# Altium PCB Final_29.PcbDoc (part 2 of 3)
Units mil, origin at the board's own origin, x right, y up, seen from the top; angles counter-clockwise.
Board outline 11000 x 6000 mil, 4 copper layers (TopLayer, MidLayer1, MidLayer2, BottomLayer), stack 29.222 mil thick; 209 components, 95 nets, 681 pads, 861 vias.
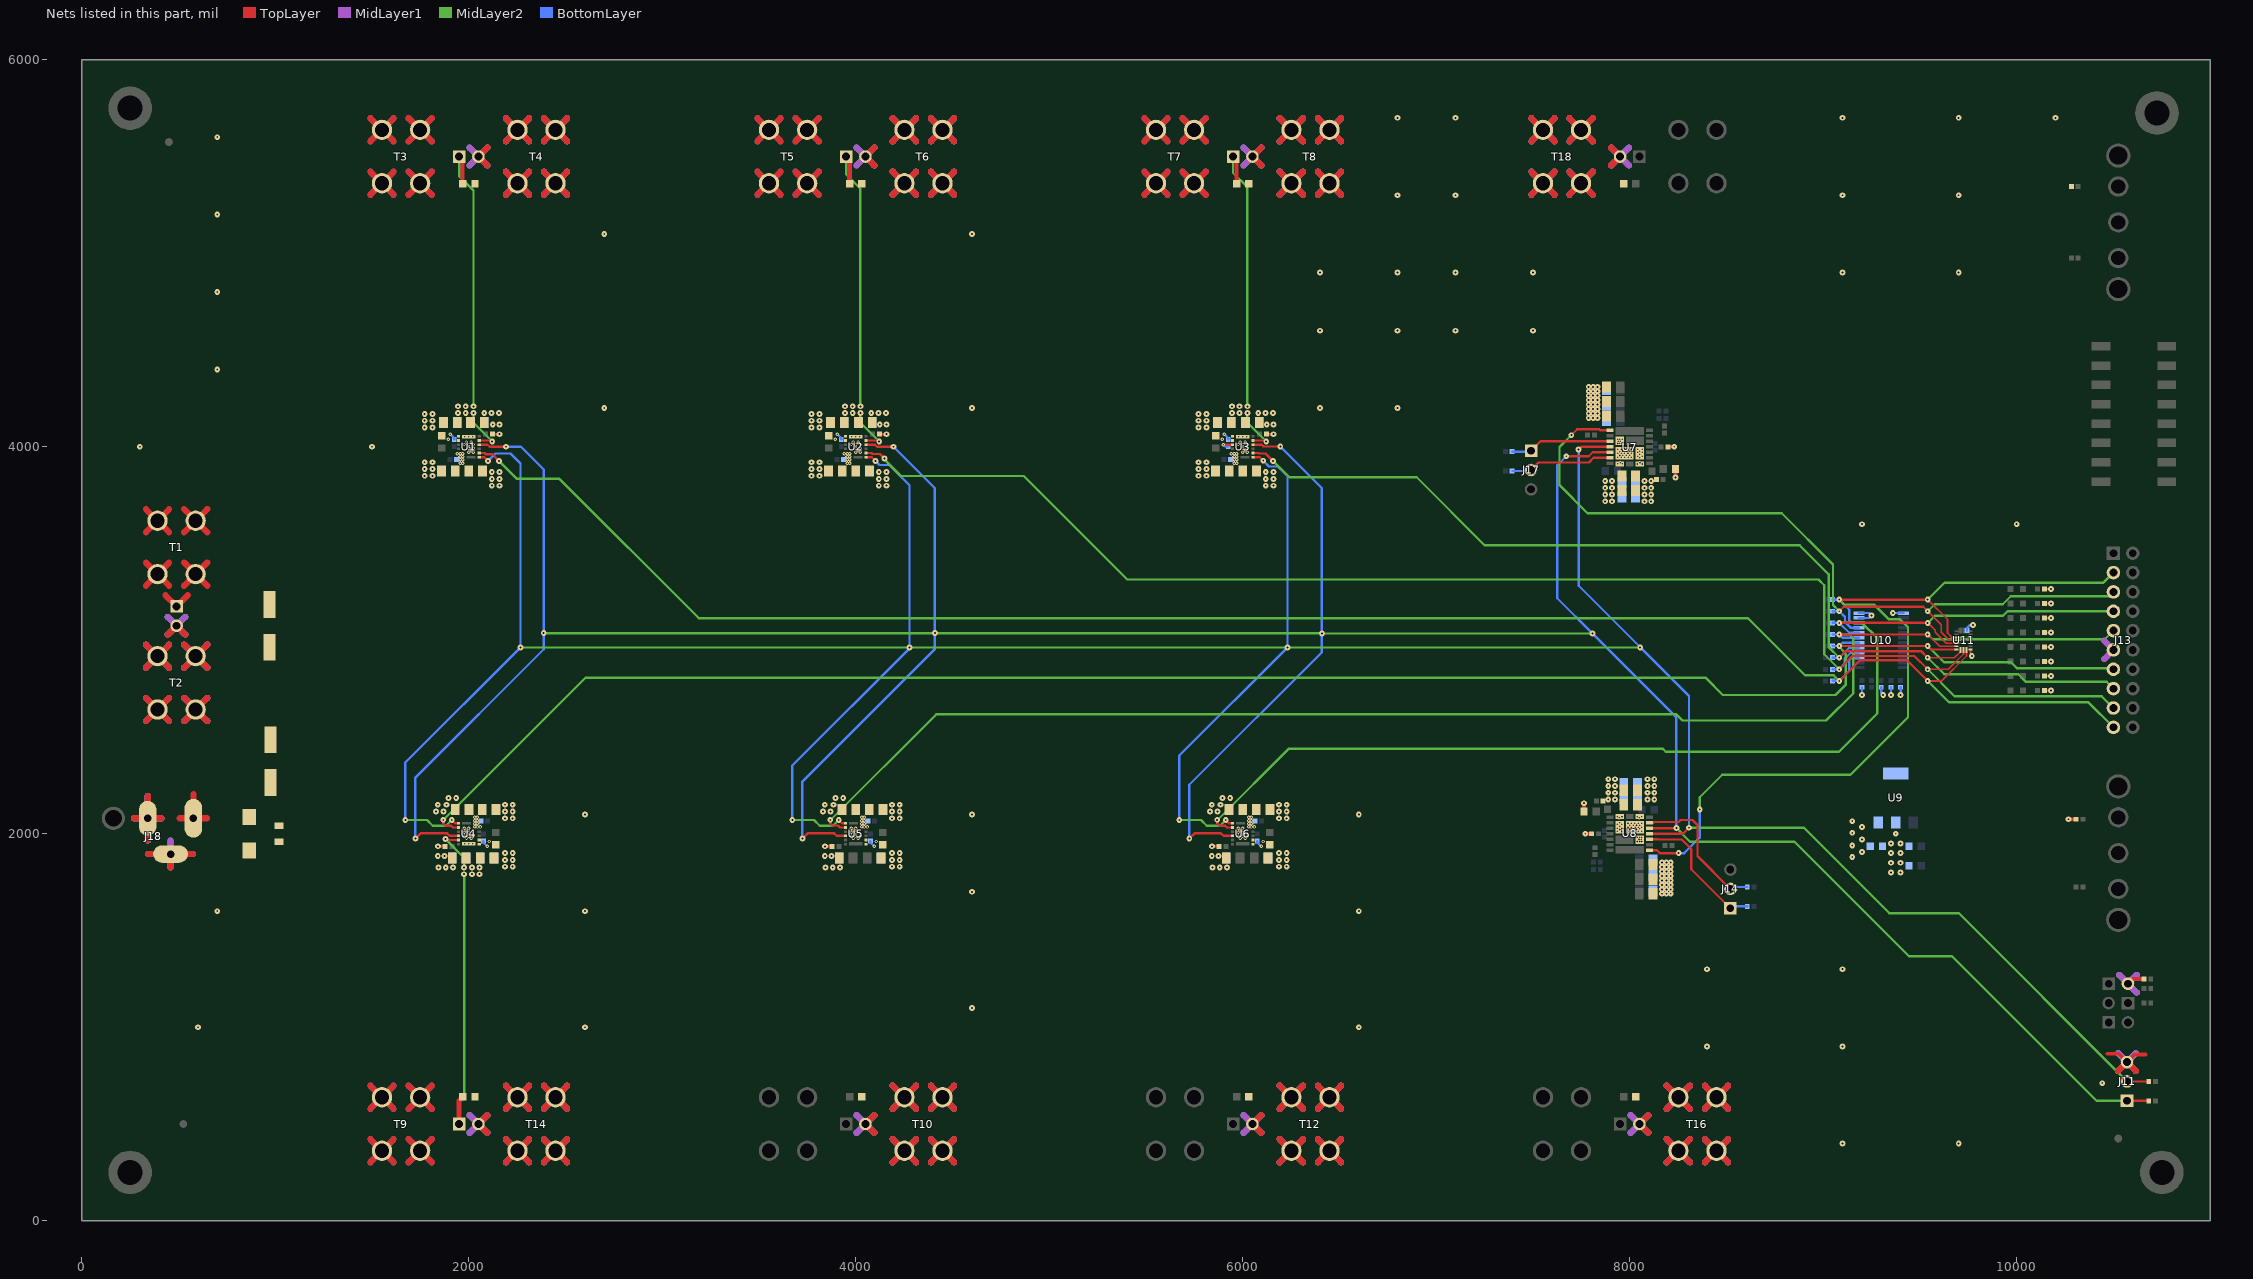
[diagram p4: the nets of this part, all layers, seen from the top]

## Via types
v1: diameter 30, hole 10, TopLayer to BottomLayer, tented both sides, 493 vias
v2: diameter 18, hole 8, TopLayer to BottomLayer, tented both sides, 308 vias
v3: diameter 18, hole 8, TopLayer to BottomLayer, tented bottom, 60 vias

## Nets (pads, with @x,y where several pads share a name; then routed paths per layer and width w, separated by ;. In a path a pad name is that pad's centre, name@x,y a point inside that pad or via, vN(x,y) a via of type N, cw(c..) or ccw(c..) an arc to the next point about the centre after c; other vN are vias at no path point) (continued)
PGND: C1.1 C2.1 C3.1 C4.2 C5.2 C7.1 C8.1 C9.1 C10.2 C11.2 C13.1 C14.1 C15.1 C16.2 C17.2 C19.1 C20.1 C21.1 C22.2 C23.2 C25.1 C26.1 C27.1 C28.1 C29.1 C30.1 C31.2 C32.2 C33.2 C34.2 C38.1 C39.1 C40.1 C41.1 C43.1 C45.1 C47.2 C48.2 C49.2 C50.2 C52.2 C53.2 C101.2 C102.1 C103.1 C104.1 C105.1 C106.1 C107.1 C108.1 C109.1 C110.1 C111.1 C112.1 C113.1 C115.1 C116.1 C118.2 C119.2 C120.2 C122.2 C123.2 C124.2 C125.1 C126.1 C128.1 C129.1 C130.1 C131.1 C132.1 C133.1 C134.1 C135.1 C136.1 C137.1 C138.2 C139.2 C140.2 C141.2 C142.2 C143.2 C144.2 C145.2 C146.2 C147.2 C148.2 C149.2 C150.2 C151.2 D15.1 J1.2 J2.2 J3.2 J4.2 J5.2 J6.2 J7.2 J8.2 J9.2 J11.3 J13.11 J18.2 J18.3 J21.2 NT1.2 NT2.1 R3.1 R6.1 R9.1 R12.1 R18.2 R23.1 R24.1 R65.1 R66.1 R67.1 R68.1 R69.1 R70.1 R71.1 R72.1 R73.1 R75.2 R76.2 T2.1 T2.2 T2.3 T2.4 T4.1 T4.2 T4.3 T4.4 T6.1 T6.2 T6.3 T6.4 T8.1 T8.2 T8.3 T8.4 T10.1 T10.2 T10.3 T10.4 T12.1 T12.2 T12.3 T12.4 T14.1 T14.2 T14.3 T14.4 T16.1 T16.2 T16.3 T16.4 T18.1 T18.2 T18.3 T18.4 U1.8 U1.9 U1.16 U2.8 U2.9 U2.16 U3.8 U3.9 U3.16 U4.8 U4.9 U4.16 U5.8 U5.9 U5.16 U6.8 U6.9 U6.16 U7.16 U7.20 U7.21 U8.16 U8.20 U8.21 U9.2 U9.4 U10.11 U10.12 U10.13 U11.11 V1.1 | length 62999.2
  TopLayer w9: U11.11@9760.7,2952.8 9760.7,2926.3 v1(9768,2919)
  TopLayer w12: v1(1841,1935) R12.1@1877.3,1935 ; R3.1@2122.7,4065 v1(2159,4065) ; v1(3841,1935) R23.1@3877.3,1935 ; R6.1@4122.7,4065 v1(4159,4065) ; v1(5841,1935) R24.1@5877.3,1935 ; R9.1@6122.7,4065 v1(6159,4065) ; R66.1@10142.7,2740 v1(10177.7,2740) ; R67.1@10142.7,2815 v1(10177.7,2815) ; R68.1@10142.7,2890 v1(10177.7,2890) ; R69.1@10142.7,2965 v1(10177.7,2965) ; R70.1@10142.7,3040 v1(10177.7,3040) ; R71.1@10142.7,3115 v1(10177.7,3115) ; R72.1@10142.7,3190 v1(10177.7,3190) ; R73.1@10142.7,3265 v1(10177.7,3265)
  TopLayer w20: C115.1@7763.5,2115 v1(7763.5,2158) ; v1(7770,2000) C116.1@7802.3,2000 ; C45.1@8197.7,4000 v1(8230,4000) ; v1(8236.5,3841) C43.1@8236.5,3885 ; v1(10267.3,2075) R75.2@10307.3,2075 ; 10468,863 10527,863 J11.3@10570,820 10610,860 10666,860 ; J21.2@10575,1225 10600,1250 R76.2@10657.3,1250
  TopLayer w32: 270.4,2080 J18.2@340.5,2080 ; 331.6,2582.1 T2.2@391.5,2642 ; 331.6,2701.9 T2.2@391.5,2642 ; 331.6,2858.1 T2.1@391.5,2918 ; 331.6,2977.9 T2.1@391.5,2918 ; 340.5,1964.9 J18.2@340.5,2080 ; 340.5,2195.1 J18.2@340.5,2080 ; 343.5,1895 J18.3@458.6,1895 ; 410.6,2080 J18.2@340.5,2080 ; 444.3,3029.3 J1.2@490,3075 535.7,3029.3 ; 451.4,2582.1 T2.2@391.5,2642 ; 451.4,2701.9 T2.2@391.5,2642 ; 451.4,2858.1 T2.1@391.5,2918 ; 451.4,2977.9 T2.1@391.5,2918 ; 458.6,1824.9 J18.3@458.6,1895 ; 528.6,2582.1 T2.3@588.5,2642 ; 528.6,2701.9 T2.3@588.5,2642 ; 528.6,2858.1 T2.4@588.5,2918 ; 528.6,2977.9 T2.4@588.5,2918 ; 573.7,1895 J18.3@458.6,1895 ; 648.4,2582.1 T2.3@588.5,2642 ; 648.4,2701.9 T2.3@588.5,2642 ; 648.4,2858.1 T2.4@588.5,2918 ; 648.4,2977.9 T2.4@588.5,2918 ; 2095.7,454.3 J5.2@2050,500 2095.7,545.7 ; 2095.7,5454.3 J2.2@2050,5500 2095.7,5545.7 ; 2191.6,302.1 T14.2@2251.5,362 ; 2191.6,421.9 T14.2@2251.5,362 ; 2191.6,578.1 T14.1@2251.5,638 ; 2191.6,697.9 T14.1@2251.5,638 ; 2191.6,5302.1 T4.2@2251.5,5362 ; 2191.6,5421.9 T4.2@2251.5,5362 ; 2191.6,5578.1 T4.1@2251.5,5638 ; 2191.6,5697.9 T4.1@2251.5,5638 ; 2311.4,302.1 T14.2@2251.5,362 ; 2311.4,421.9 T14.2@2251.5,362 ; 2311.4,578.1 T14.1@2251.5,638 ; 2311.4,697.9 T14.1@2251.5,638 ; 2311.4,5302.1 T4.2@2251.5,5362 ; 2311.4,5421.9 T4.2@2251.5,5362 ; 2311.4,5578.1 T4.1@2251.5,5638 ; 2311.4,5697.9 T4.1@2251.5,5638 ; 2388.6,302.1 T14.3@2448.5,362 ; 2388.6,421.9 T14.3@2448.5,362 ; 2388.6,578.1 T14.4@2448.5,638 ; 2388.6,697.9 T14.4@2448.5,638 ; 2388.6,5302.1 T4.3@2448.5,5362 ; 2388.6,5421.9 T4.3@2448.5,5362 ; 2388.6,5578.1 T4.4@2448.5,5638 ; 2388.6,5697.9 T4.4@2448.5,5638 ; 2508.4,302.1 T14.3@2448.5,362 ; 2508.4,421.9 T14.3@2448.5,362 ; 2508.4,578.1 T14.4@2448.5,638 ; 2508.4,697.9 T14.4@2448.5,638 ; 2508.4,5302.1 T4.3@2448.5,5362 ; 2508.4,5421.9 T4.3@2448.5,5362 ; 2508.4,5578.1 T4.4@2448.5,5638 ; 2508.4,5697.9 T4.4@2448.5,5638 ; 4095.7,454.3 J6.2@4050,500 4095.7,545.7 ; 4095.7,5454.3 J3.2@4050,5500 4095.7,5545.7 ; 4191.6,302.1 T10.2@4251.5,362 ; 4191.6,421.9 T10.2@4251.5,362 ; 4191.6,578.1 T10.1@4251.5,638 ; 4191.6,697.9 T10.1@4251.5,638 ; 4191.6,5302.1 T6.2@4251.5,5362 ; 4191.6,5421.9 T6.2@4251.5,5362 ; 4191.6,5578.1 T6.1@4251.5,5638 ; 4191.6,5697.9 T6.1@4251.5,5638 ; 4311.4,302.1 T10.2@4251.5,362 ; 4311.4,421.9 T10.2@4251.5,362 ; 4311.4,578.1 T10.1@4251.5,638 ; 4311.4,697.9 T10.1@4251.5,638 ; 4311.4,5302.1 T6.2@4251.5,5362 ; 4311.4,5421.9 T6.2@4251.5,5362 ; 4311.4,5578.1 T6.1@4251.5,5638 ; 4311.4,5697.9 T6.1@4251.5,5638 ; 4388.6,302.1 T10.3@4448.5,362 ; 4388.6,421.9 T10.3@4448.5,362 ; 4388.6,578.1 T10.4@4448.5,638 ; 4388.6,697.9 T10.4@4448.5,638 ; 4388.6,5302.1 T6.3@4448.5,5362 ; 4388.6,5421.9 T6.3@4448.5,5362 ; 4388.6,5578.1 T6.4@4448.5,5638 ; 4388.6,5697.9 T6.4@4448.5,5638 ; 4508.4,302.1 T10.3@4448.5,362 ; 4508.4,421.9 T10.3@4448.5,362 ; 4508.4,578.1 T10.4@4448.5,638 ; 4508.4,697.9 T10.4@4448.5,638 ; 4508.4,5302.1 T6.3@4448.5,5362 ; 4508.4,5421.9 T6.3@4448.5,5362 ; 4508.4,5578.1 T6.4@4448.5,5638 ; 4508.4,5697.9 T6.4@4448.5,5638 ; 6095.7,454.3 J7.2@6050,500 6095.7,545.7 ; 6095.7,5454.3 J4.2@6050,5500 6095.7,5545.7 ; 6191.6,302.1 T12.2@6251.5,362 ; 6191.6,421.9 T12.2@6251.5,362 ; 6191.6,578.1 T12.1@6251.5,638 ; 6191.6,697.9 T12.1@6251.5,638 ; 6191.6,5302.1 T8.2@6251.5,5362 ; 6191.6,5421.9 T8.2@6251.5,5362 ; 6191.6,5578.1 T8.1@6251.5,5638 ; 6191.6,5697.9 T8.1@6251.5,5638 ; 6311.4,302.1 T12.2@6251.5,362 ; 6311.4,421.9 T12.2@6251.5,362 ; 6311.4,578.1 T12.1@6251.5,638 ; 6311.4,697.9 T12.1@6251.5,638 ; 6311.4,5302.1 T8.2@6251.5,5362 ; 6311.4,5421.9 T8.2@6251.5,5362 ; 6311.4,5578.1 T8.1@6251.5,5638 ; 6311.4,5697.9 T8.1@6251.5,5638 ; 6388.6,302.1 T12.3@6448.5,362 ; 6388.6,421.9 T12.3@6448.5,362 ; 6388.6,578.1 T12.4@6448.5,638 ; 6388.6,697.9 T12.4@6448.5,638 ; 6388.6,5302.1 T8.3@6448.5,5362 ; 6388.6,5421.9 T8.3@6448.5,5362 ; 6388.6,5578.1 T8.4@6448.5,5638 ; 6388.6,5697.9 T8.4@6448.5,5638 ; 6508.4,302.1 T12.3@6448.5,362 ; 6508.4,421.9 T12.3@6448.5,362 ; 6508.4,578.1 T12.4@6448.5,638 ; 6508.4,697.9 T12.4@6448.5,638 ; 6508.4,5302.1 T8.3@6448.5,5362 ; 6508.4,5421.9 T8.3@6448.5,5362 ; 6508.4,5578.1 T8.4@6448.5,5638 ; 6508.4,5697.9 T8.4@6448.5,5638 ; 7491.6,5302.1 T18.2@7551.5,5362 ; 7491.6,5421.9 T18.2@7551.5,5362 ; 7491.6,5578.1 T18.1@7551.5,5638 ; 7491.6,5697.9 T18.1@7551.5,5638 ; 7611.4,5302.1 T18.2@7551.5,5362 ; 7611.4,5421.9 T18.2@7551.5,5362 ; 7611.4,5578.1 T18.1@7551.5,5638 ; 7611.4,5697.9 T18.1@7551.5,5638 ; 7688.6,5302.1 T18.3@7748.5,5362 ; 7688.6,5421.9 T18.3@7748.5,5362 ; 7688.6,5578.1 T18.4@7748.5,5638 ; 7688.6,5697.9 T18.4@7748.5,5638 ; 7808.4,5302.1 T18.3@7748.5,5362 ; 7808.4,5421.9 T18.3@7748.5,5362 ; 7808.4,5578.1 T18.4@7748.5,5638 ; 7808.4,5697.9 T18.4@7748.5,5638 ; 7904.3,5454.3 J9.2@7950,5500 7904.3,5545.7 ; 8095.7,454.3 J8.2@8050,500 8095.7,545.7 ; 8191.6,302.1 T16.2@8251.5,362 ; 8191.6,421.9 T16.2@8251.5,362 ; 8191.6,578.1 T16.1@8251.5,638 ; 8191.6,697.9 T16.1@8251.5,638 ; 8311.4,302.1 T16.2@8251.5,362 ; 8311.4,421.9 T16.2@8251.5,362 ; 8311.4,578.1 T16.1@8251.5,638 ; 8311.4,697.9 T16.1@8251.5,638 ; 8388.6,302.1 T16.3@8448.5,362 ; 8388.6,421.9 T16.3@8448.5,362 ; 8388.6,578.1 T16.4@8448.5,638 ; 8388.6,697.9 T16.4@8448.5,638 ; 8508.4,302.1 T16.3@8448.5,362 ; 8508.4,421.9 T16.3@8448.5,362 ; 8508.4,578.1 T16.4@8448.5,638 ; 8508.4,697.9 T16.4@8448.5,638 ; 10524.3,774.3 J11.3@10570,820 10615.7,774.3
  MidLayer1 w32: 270.4,2080 J18.2@340.5,2080 ; 331.6,2582.1 T2.2@391.5,2642 ; 331.6,2701.9 T2.2@391.5,2642 ; 331.6,2858.1 T2.1@391.5,2918 ; 331.6,2977.9 T2.1@391.5,2918 ; 340.5,1964.9 J18.2@340.5,2080 ; 340.5,2195.1 J18.2@340.5,2080 ; 343.5,1895 J18.3@458.6,1895 ; 410.6,2080 J18.2@340.5,2080 ; 444.3,3029.3 J1.2@490,3075 ; 444.3,3120.7 J1.2@490,3075 ; 451.4,2582.1 T2.2@391.5,2642 ; 451.4,2701.9 T2.2@391.5,2642 ; 451.4,2858.1 T2.1@391.5,2918 ; 451.4,2977.9 T2.1@391.5,2918 ; 458.6,1824.9 J18.3@458.6,1895 ; 458.6,1965.1 J18.3@458.6,1895 ; 528.6,2582.1 T2.3@588.5,2642 ; 528.6,2701.9 T2.3@588.5,2642 ; 528.6,2858.1 T2.4@588.5,2918 ; 528.6,2977.9 T2.4@588.5,2918 ; 535.7,3029.3 J1.2@490,3075 ; 535.7,3120.7 J1.2@490,3075 ; 573.7,1895 J18.3@458.6,1895 ; 648.4,2582.1 T2.3@588.5,2642 ; 648.4,2701.9 T2.3@588.5,2642 ; 648.4,2858.1 T2.4@588.5,2918 ; 648.4,2977.9 T2.4@588.5,2918 ; 2004.3,454.3 J5.2@2050,500 ; 2004.3,545.7 J5.2@2050,500 ; 2004.3,5454.3 J2.2@2050,5500 ; 2004.3,5545.7 J2.2@2050,5500 ; 2095.7,454.3 J5.2@2050,500 ; 2095.7,545.7 J5.2@2050,500 ; 2095.7,5454.3 J2.2@2050,5500 ; 2095.7,5545.7 J2.2@2050,5500 ; 2191.6,302.1 T14.2@2251.5,362 ; 2191.6,421.9 T14.2@2251.5,362 ; 2191.6,578.1 T14.1@2251.5,638 ; 2191.6,697.9 T14.1@2251.5,638 ; 2191.6,5302.1 T4.2@2251.5,5362 ; 2191.6,5421.9 T4.2@2251.5,5362 ; 2191.6,5578.1 T4.1@2251.5,5638 ; 2191.6,5697.9 T4.1@2251.5,5638 ; 2311.4,302.1 T14.2@2251.5,362 ; 2311.4,421.9 T14.2@2251.5,362 ; 2311.4,578.1 T14.1@2251.5,638 ; 2311.4,697.9 T14.1@2251.5,638 ; 2311.4,5302.1 T4.2@2251.5,5362 ; 2311.4,5421.9 T4.2@2251.5,5362 ; 2311.4,5578.1 T4.1@2251.5,5638 ; 2311.4,5697.9 T4.1@2251.5,5638 ; 2388.6,302.1 T14.3@2448.5,362 ; 2388.6,421.9 T14.3@2448.5,362 ; 2388.6,578.1 T14.4@2448.5,638 ; 2388.6,697.9 T14.4@2448.5,638 ; 2388.6,5302.1 T4.3@2448.5,5362 ; 2388.6,5421.9 T4.3@2448.5,5362 ; 2388.6,5578.1 T4.4@2448.5,5638 ; 2388.6,5697.9 T4.4@2448.5,5638 ; 2508.4,302.1 T14.3@2448.5,362 ; 2508.4,421.9 T14.3@2448.5,362 ; 2508.4,578.1 T14.4@2448.5,638 ; 2508.4,697.9 T14.4@2448.5,638 ; 2508.4,5302.1 T4.3@2448.5,5362 ; 2508.4,5421.9 T4.3@2448.5,5362 ; 2508.4,5578.1 T4.4@2448.5,5638 ; 2508.4,5697.9 T4.4@2448.5,5638 ; 4004.3,454.3 J6.2@4050,500 ; 4004.3,545.7 J6.2@4050,500 ; 4004.3,5454.3 J3.2@4050,5500 ; 4004.3,5545.7 J3.2@4050,5500 ; 4095.7,454.3 J6.2@4050,500 ; 4095.7,545.7 J6.2@4050,500 ; 4095.7,5454.3 J3.2@4050,5500 ; 4095.7,5545.7 J3.2@4050,5500 ; 4191.6,302.1 T10.2@4251.5,362 ; 4191.6,421.9 T10.2@4251.5,362 ; 4191.6,578.1 T10.1@4251.5,638 ; 4191.6,697.9 T10.1@4251.5,638 ; 4191.6,5302.1 T6.2@4251.5,5362 ; 4191.6,5421.9 T6.2@4251.5,5362 ; 4191.6,5578.1 T6.1@4251.5,5638 ; 4191.6,5697.9 T6.1@4251.5,5638 ; 4311.4,302.1 T10.2@4251.5,362 ; 4311.4,421.9 T10.2@4251.5,362 ; 4311.4,578.1 T10.1@4251.5,638 ; 4311.4,697.9 T10.1@4251.5,638 ; 4311.4,5302.1 T6.2@4251.5,5362 ; 4311.4,5421.9 T6.2@4251.5,5362 ; 4311.4,5578.1 T6.1@4251.5,5638 ; 4311.4,5697.9 T6.1@4251.5,5638 ; 4388.6,302.1 T10.3@4448.5,362 ; 4388.6,421.9 T10.3@4448.5,362 ; 4388.6,578.1 T10.4@4448.5,638 ; 4388.6,697.9 T10.4@4448.5,638 ; 4388.6,5302.1 T6.3@4448.5,5362 ; 4388.6,5421.9 T6.3@4448.5,5362 ; 4388.6,5578.1 T6.4@4448.5,5638 ; 4388.6,5697.9 T6.4@4448.5,5638 ; 4508.4,302.1 T10.3@4448.5,362 ; 4508.4,421.9 T10.3@4448.5,362 ; 4508.4,578.1 T10.4@4448.5,638 ; 4508.4,697.9 T10.4@4448.5,638 ; 4508.4,5302.1 T6.3@4448.5,5362 ; 4508.4,5421.9 T6.3@4448.5,5362 ; 4508.4,5578.1 T6.4@4448.5,5638 ; 4508.4,5697.9 T6.4@4448.5,5638 ; 6004.3,454.3 J7.2@6050,500 ; 6004.3,545.7 J7.2@6050,500 ; 6004.3,5454.3 J4.2@6050,5500 ; 6004.3,5545.7 J4.2@6050,5500 ; 6095.7,454.3 J7.2@6050,500 ; 6095.7,545.7 J7.2@6050,500 ; 6095.7,5454.3 J4.2@6050,5500 ; 6095.7,5545.7 J4.2@6050,5500 ; 6191.6,302.1 T12.2@6251.5,362 ; 6191.6,421.9 T12.2@6251.5,362 ; 6191.6,578.1 T12.1@6251.5,638 ; 6191.6,697.9 T12.1@6251.5,638 ; 6191.6,5302.1 T8.2@6251.5,5362 ; 6191.6,5421.9 T8.2@6251.5,5362 ; 6191.6,5578.1 T8.1@6251.5,5638 ; 6191.6,5697.9 T8.1@6251.5,5638 ; 6311.4,302.1 T12.2@6251.5,362 ; 6311.4,421.9 T12.2@6251.5,362 ; 6311.4,578.1 T12.1@6251.5,638 ; 6311.4,697.9 T12.1@6251.5,638 ; 6311.4,5302.1 T8.2@6251.5,5362 ; 6311.4,5421.9 T8.2@6251.5,5362 ; 6311.4,5578.1 T8.1@6251.5,5638 ; 6311.4,5697.9 T8.1@6251.5,5638 ; 6388.6,302.1 T12.3@6448.5,362 ; 6388.6,421.9 T12.3@6448.5,362 ; 6388.6,578.1 T12.4@6448.5,638 ; 6388.6,697.9 T12.4@6448.5,638 ; 6388.6,5302.1 T8.3@6448.5,5362 ; 6388.6,5421.9 T8.3@6448.5,5362 ; 6388.6,5578.1 T8.4@6448.5,5638 ; 6388.6,5697.9 T8.4@6448.5,5638 ; 6508.4,302.1 T12.3@6448.5,362 ; 6508.4,421.9 T12.3@6448.5,362 ; 6508.4,578.1 T12.4@6448.5,638 ; 6508.4,697.9 T12.4@6448.5,638 ; 6508.4,5302.1 T8.3@6448.5,5362 ; 6508.4,5421.9 T8.3@6448.5,5362 ; 6508.4,5578.1 T8.4@6448.5,5638 ; 6508.4,5697.9 T8.4@6448.5,5638 ; 7491.6,5302.1 T18.2@7551.5,5362 ; 7491.6,5421.9 T18.2@7551.5,5362 ; 7491.6,5578.1 T18.1@7551.5,5638 ; 7491.6,5697.9 T18.1@7551.5,5638 ; 7611.4,5302.1 T18.2@7551.5,5362 ; 7611.4,5421.9 T18.2@7551.5,5362 ; 7611.4,5578.1 T18.1@7551.5,5638 ; 7611.4,5697.9 T18.1@7551.5,5638 ; 7688.6,5302.1 T18.3@7748.5,5362 ; 7688.6,5421.9 T18.3@7748.5,5362 ; 7688.6,5578.1 T18.4@7748.5,5638 ; 7688.6,5697.9 T18.4@7748.5,5638 ; 7808.4,5302.1 T18.3@7748.5,5362 ; 7808.4,5421.9 T18.3@7748.5,5362 ; 7808.4,5578.1 T18.4@7748.5,5638 ; 7808.4,5697.9 T18.4@7748.5,5638 ; 7904.3,5454.3 J9.2@7950,5500 ; 7904.3,5545.7 J9.2@7950,5500 ; 7995.7,5454.3 J9.2@7950,5500 ; 7995.7,5545.7 J9.2@7950,5500 ; 8004.3,454.3 J8.2@8050,500 ; 8004.3,545.7 J8.2@8050,500 ; 8095.7,454.3 J8.2@8050,500 ; 8095.7,545.7 J8.2@8050,500 ; 8191.6,302.1 T16.2@8251.5,362 ; 8191.6,421.9 T16.2@8251.5,362 ; 8191.6,578.1 T16.1@8251.5,638 ; 8191.6,697.9 T16.1@8251.5,638 ; 8311.4,302.1 T16.2@8251.5,362 ; 8311.4,421.9 T16.2@8251.5,362 ; 8311.4,578.1 T16.1@8251.5,638 ; 8311.4,697.9 T16.1@8251.5,638 ; 8388.6,302.1 T16.3@8448.5,362 ; 8388.6,421.9 T16.3@8448.5,362 ; 8388.6,578.1 T16.4@8448.5,638 ; 8388.6,697.9 T16.4@8448.5,638 ; 8508.4,302.1 T16.3@8448.5,362 ; 8508.4,421.9 T16.3@8448.5,362 ; 8508.4,578.1 T16.4@8448.5,638 ; 8508.4,697.9 T16.4@8448.5,638 ; 10452.5,2902.5 J13.11@10500,2950 10452.5,2997.5 ; 10524.3,774.3 J11.3@10570,820 ; 10524.3,865.7 J11.3@10570,820 ; 10529.3,1270.7 J21.2@10575,1225 ; 10615.7,774.3 J11.3@10570,820 ; 10615.7,865.7 J11.3@10570,820 ; 10620.7,1179.3 J21.2@10575,1225 ; 10620.7,1270.7 J21.2@10575,1225
  MidLayer2 w32: 270.4,2080 J18.2@340.5,2080 ; 331.6,2582.1 T2.2@391.5,2642 ; 331.6,2701.9 T2.2@391.5,2642 ; 331.6,2858.1 T2.1@391.5,2918 ; 331.6,2977.9 T2.1@391.5,2918 ; 340.5,1964.9 J18.2@340.5,2080 ; 340.5,2195.1 J18.2@340.5,2080 ; 343.5,1895 J18.3@458.6,1895 ; 410.6,2080 J18.2@340.5,2080 ; 444.3,3029.3 J1.2@490,3075 ; 444.3,3120.7 J1.2@490,3075 ; 451.4,2582.1 T2.2@391.5,2642 ; 451.4,2701.9 T2.2@391.5,2642 ; 451.4,2858.1 T2.1@391.5,2918 ; 451.4,2977.9 T2.1@391.5,2918 ; 458.6,1824.9 J18.3@458.6,1895 ; 458.6,1965.1 J18.3@458.6,1895 ; 528.6,2582.1 T2.3@588.5,2642 ; 528.6,2701.9 T2.3@588.5,2642 ; 528.6,2858.1 T2.4@588.5,2918 ; 528.6,2977.9 T2.4@588.5,2918 ; 535.7,3029.3 J1.2@490,3075 ; 535.7,3120.7 J1.2@490,3075 ; 573.7,1895 J18.3@458.6,1895 ; 648.4,2582.1 T2.3@588.5,2642 ; 648.4,2701.9 T2.3@588.5,2642 ; 648.4,2858.1 T2.4@588.5,2918 ; 648.4,2977.9 T2.4@588.5,2918 ; 2004.3,454.3 J5.2@2050,500 ; 2004.3,545.7 J5.2@2050,500 ; 2004.3,5454.3 J2.2@2050,5500 ; 2004.3,5545.7 J2.2@2050,5500 ; 2095.7,454.3 J5.2@2050,500 ; 2095.7,545.7 J5.2@2050,500 ; 2095.7,5454.3 J2.2@2050,5500 ; 2095.7,5545.7 J2.2@2050,5500 ; 2191.6,302.1 T14.2@2251.5,362 ; 2191.6,421.9 T14.2@2251.5,362 ; 2191.6,578.1 T14.1@2251.5,638 ; 2191.6,697.9 T14.1@2251.5,638 ; 2191.6,5302.1 T4.2@2251.5,5362 ; 2191.6,5421.9 T4.2@2251.5,5362 ; 2191.6,5578.1 T4.1@2251.5,5638 ; 2191.6,5697.9 T4.1@2251.5,5638 ; 2311.4,302.1 T14.2@2251.5,362 ; 2311.4,421.9 T14.2@2251.5,362 ; 2311.4,578.1 T14.1@2251.5,638 ; 2311.4,697.9 T14.1@2251.5,638 ; 2311.4,5302.1 T4.2@2251.5,5362 ; 2311.4,5421.9 T4.2@2251.5,5362 ; 2311.4,5578.1 T4.1@2251.5,5638 ; 2311.4,5697.9 T4.1@2251.5,5638 ; 2388.6,302.1 T14.3@2448.5,362 ; 2388.6,421.9 T14.3@2448.5,362 ; 2388.6,578.1 T14.4@2448.5,638 ; 2388.6,697.9 T14.4@2448.5,638 ; 2388.6,5302.1 T4.3@2448.5,5362 ; 2388.6,5421.9 T4.3@2448.5,5362 ; 2388.6,5578.1 T4.4@2448.5,5638 ; 2388.6,5697.9 T4.4@2448.5,5638 ; 2508.4,302.1 T14.3@2448.5,362 ; 2508.4,421.9 T14.3@2448.5,362 ; 2508.4,578.1 T14.4@2448.5,638 ; 2508.4,697.9 T14.4@2448.5,638 ; 2508.4,5302.1 T4.3@2448.5,5362 ; 2508.4,5421.9 T4.3@2448.5,5362 ; 2508.4,5578.1 T4.4@2448.5,5638 ; 2508.4,5697.9 T4.4@2448.5,5638 ; 4004.3,454.3 J6.2@4050,500 ; 4004.3,545.7 J6.2@4050,500 ; 4004.3,5454.3 J3.2@4050,5500 ; 4004.3,5545.7 J3.2@4050,5500 ; 4095.7,454.3 J6.2@4050,500 ; 4095.7,545.7 J6.2@4050,500 ; 4095.7,5454.3 J3.2@4050,5500 ; 4095.7,5545.7 J3.2@4050,5500 ; 4191.6,302.1 T10.2@4251.5,362 ; 4191.6,421.9 T10.2@4251.5,362 ; 4191.6,578.1 T10.1@4251.5,638 ; 4191.6,697.9 T10.1@4251.5,638 ; 4191.6,5302.1 T6.2@4251.5,5362 ; 4191.6,5421.9 T6.2@4251.5,5362 ; 4191.6,5578.1 T6.1@4251.5,5638 ; 4191.6,5697.9 T6.1@4251.5,5638 ; 4311.4,302.1 T10.2@4251.5,362 ; 4311.4,421.9 T10.2@4251.5,362 ; 4311.4,578.1 T10.1@4251.5,638 ; 4311.4,697.9 T10.1@4251.5,638 ; 4311.4,5302.1 T6.2@4251.5,5362 ; 4311.4,5421.9 T6.2@4251.5,5362 ; 4311.4,5578.1 T6.1@4251.5,5638 ; 4311.4,5697.9 T6.1@4251.5,5638 ; 4388.6,302.1 T10.3@4448.5,362 ; 4388.6,421.9 T10.3@4448.5,362 ; 4388.6,578.1 T10.4@4448.5,638 ; 4388.6,697.9 T10.4@4448.5,638 ; 4388.6,5302.1 T6.3@4448.5,5362 ; 4388.6,5421.9 T6.3@4448.5,5362 ; 4388.6,5578.1 T6.4@4448.5,5638 ; 4388.6,5697.9 T6.4@4448.5,5638 ; 4508.4,302.1 T10.3@4448.5,362 ; 4508.4,421.9 T10.3@4448.5,362 ; 4508.4,578.1 T10.4@4448.5,638 ; 4508.4,697.9 T10.4@4448.5,638 ; 4508.4,5302.1 T6.3@4448.5,5362 ; 4508.4,5421.9 T6.3@4448.5,5362 ; 4508.4,5578.1 T6.4@4448.5,5638 ; 4508.4,5697.9 T6.4@4448.5,5638 ; 6004.3,454.3 J7.2@6050,500 ; 6004.3,545.7 J7.2@6050,500 ; 6004.3,5454.3 J4.2@6050,5500 ; 6004.3,5545.7 J4.2@6050,5500 ; 6095.7,454.3 J7.2@6050,500 ; 6095.7,545.7 J7.2@6050,500 ; 6095.7,5454.3 J4.2@6050,5500 ; 6095.7,5545.7 J4.2@6050,5500 ; 6191.6,302.1 T12.2@6251.5,362 ; 6191.6,421.9 T12.2@6251.5,362 ; 6191.6,578.1 T12.1@6251.5,638 ; 6191.6,697.9 T12.1@6251.5,638 ; 6191.6,5302.1 T8.2@6251.5,5362 ; 6191.6,5421.9 T8.2@6251.5,5362 ; 6191.6,5578.1 T8.1@6251.5,5638 ; 6191.6,5697.9 T8.1@6251.5,5638 ; 6311.4,302.1 T12.2@6251.5,362 ; 6311.4,421.9 T12.2@6251.5,362 ; 6311.4,578.1 T12.1@6251.5,638 ; 6311.4,697.9 T12.1@6251.5,638 ; 6311.4,5302.1 T8.2@6251.5,5362 ; 6311.4,5421.9 T8.2@6251.5,5362 ; 6311.4,5578.1 T8.1@6251.5,5638 ; 6311.4,5697.9 T8.1@6251.5,5638 ; 6388.6,302.1 T12.3@6448.5,362 ; 6388.6,421.9 T12.3@6448.5,362 ; 6388.6,578.1 T12.4@6448.5,638 ; 6388.6,697.9 T12.4@6448.5,638 ; 6388.6,5302.1 T8.3@6448.5,5362 ; 6388.6,5421.9 T8.3@6448.5,5362 ; 6388.6,5578.1 T8.4@6448.5,5638 ; 6388.6,5697.9 T8.4@6448.5,5638 ; 6508.4,302.1 T12.3@6448.5,362 ; 6508.4,421.9 T12.3@6448.5,362 ; 6508.4,578.1 T12.4@6448.5,638 ; 6508.4,697.9 T12.4@6448.5,638 ; 6508.4,5302.1 T8.3@6448.5,5362 ; 6508.4,5421.9 T8.3@6448.5,5362 ; 6508.4,5578.1 T8.4@6448.5,5638 ; 6508.4,5697.9 T8.4@6448.5,5638 ; 7491.6,5302.1 T18.2@7551.5,5362 ; 7491.6,5421.9 T18.2@7551.5,5362 ; 7491.6,5578.1 T18.1@7551.5,5638 ; 7491.6,5697.9 T18.1@7551.5,5638 ; 7611.4,5302.1 T18.2@7551.5,5362 ; 7611.4,5421.9 T18.2@7551.5,5362 ; 7611.4,5578.1 T18.1@7551.5,5638 ; 7611.4,5697.9 T18.1@7551.5,5638 ; 7688.6,5302.1 T18.3@7748.5,5362 ; 7688.6,5421.9 T18.3@7748.5,5362 ; 7688.6,5578.1 T18.4@7748.5,5638 ; 7688.6,5697.9 T18.4@7748.5,5638 ; 7808.4,5302.1 T18.3@7748.5,5362 ; 7808.4,5421.9 T18.3@7748.5,5362 ; 7808.4,5578.1 T18.4@7748.5,5638 ; 7808.4,5697.9 T18.4@7748.5,5638 ; 7904.3,5454.3 J9.2@7950,5500 ; 7904.3,5545.7 J9.2@7950,5500 ; 7995.7,5454.3 J9.2@7950,5500 ; 7995.7,5545.7 J9.2@7950,5500 ; 8004.3,454.3 J8.2@8050,500 ; 8004.3,545.7 J8.2@8050,500 ; 8095.7,454.3 J8.2@8050,500 ; 8095.7,545.7 J8.2@8050,500 ; 8191.6,302.1 T16.2@8251.5,362 ; 8191.6,421.9 T16.2@8251.5,362 ; 8191.6,578.1 T16.1@8251.5,638 ; 8191.6,697.9 T16.1@8251.5,638 ; 8311.4,302.1 T16.2@8251.5,362 ; 8311.4,421.9 T16.2@8251.5,362 ; 8311.4,578.1 T16.1@8251.5,638 ; 8311.4,697.9 T16.1@8251.5,638 ; 8388.6,302.1 T16.3@8448.5,362 ; 8388.6,421.9 T16.3@8448.5,362 ; 8388.6,578.1 T16.4@8448.5,638 ; 8388.6,697.9 T16.4@8448.5,638 ; 8508.4,302.1 T16.3@8448.5,362 ; 8508.4,421.9 T16.3@8448.5,362 ; 8508.4,578.1 T16.4@8448.5,638 ; 8508.4,697.9 T16.4@8448.5,638 ; 10524.3,865.7 J11.3@10570,820 ; 10615.7,774.3 J11.3@10570,820 ; 10615.7,865.7 J11.3@10570,820 ; 10620.7,1179.3 J21.2@10575,1225 10620.7,1270.7
  BottomLayer w12: v2(1905,4065) 1925,4045 C134.1@1925,4037.7 ; C135.1@2075,1962.3 2075,1955 v2(2095,1935) ; v2(3905,4065) 3925,4045 C132.1@3925,4037.7 ; C137.1@4075,1962.3 4075,1955 v2(4095,1935) ; v2(5905,4065) 5925,4045 C133.1@5925,4037.7 ; C136.1@6075,1962.3 6075,1955 v2(6095,1935) ; U10.11@9183.9,3115.2 9236.2,3115.2 v1(9249,3128) 9236.3,3140.7 U10.12@9183.9,3140.7 ; v1(9200,2717.3) C130.1@9200,2757.3 ; R65.1@9300,2757.3 9300,2727.3 v1(9310,2717.3) ; v1(9350,2717.3) C129.1@9350,2757.3 ; v1(9359.7,3140.7) U10.13@9416.1,3140.7 ; v1(9400,2717.3) C128.1@9400,2757.3 ; C151.2@9742.7,3050 9742.7,3063.7 9758,3079 v1(9774,3079)
  BottomLayer w32: 270.4,2080 J18.2@340.5,2080 ; 331.6,2582.1 T2.2@391.5,2642 ; 331.6,2701.9 T2.2@391.5,2642 ; 331.6,2858.1 T2.1@391.5,2918 ; 331.6,2977.9 T2.1@391.5,2918 ; 340.5,1964.9 J18.2@340.5,2080 ; 340.5,2195.1 J18.2@340.5,2080 ; 343.5,1895 J18.3@458.6,1895 ; 410.6,2080 J18.2@340.5,2080 ; 444.3,3029.3 J1.2@490,3075 ; 444.3,3120.7 J1.2@490,3075 ; 451.4,2582.1 T2.2@391.5,2642 ; 451.4,2701.9 T2.2@391.5,2642 ; 451.4,2858.1 T2.1@391.5,2918 ; 451.4,2977.9 T2.1@391.5,2918 ; 458.6,1824.9 J18.3@458.6,1895 ; 458.6,1965.1 J18.3@458.6,1895 ; 528.6,2582.1 T2.3@588.5,2642 ; 528.6,2701.9 T2.3@588.5,2642 ; 528.6,2858.1 T2.4@588.5,2918 ; 528.6,2977.9 T2.4@588.5,2918 ; 535.7,3029.3 J1.2@490,3075 ; 535.7,3120.7 J1.2@490,3075 ; 573.7,1895 J18.3@458.6,1895 ; 648.4,2582.1 T2.3@588.5,2642 ; 648.4,2701.9 T2.3@588.5,2642 ; 648.4,2858.1 T2.4@588.5,2918 ; 648.4,2977.9 T2.4@588.5,2918 ; 2004.3,454.3 J5.2@2050,500 ; 2004.3,545.7 J5.2@2050,500 ; 2004.3,5454.3 J2.2@2050,5500 ; 2004.3,5545.7 J2.2@2050,5500 ; 2095.7,454.3 J5.2@2050,500 ; 2095.7,545.7 J5.2@2050,500 ; 2095.7,5454.3 J2.2@2050,5500 ; 2095.7,5545.7 J2.2@2050,5500 ; 2191.6,302.1 T14.2@2251.5,362 ; 2191.6,421.9 T14.2@2251.5,362 ; 2191.6,578.1 T14.1@2251.5,638 ; 2191.6,697.9 T14.1@2251.5,638 ; 2191.6,5302.1 T4.2@2251.5,5362 ; 2191.6,5421.9 T4.2@2251.5,5362 ; 2191.6,5578.1 T4.1@2251.5,5638 ; 2191.6,5697.9 T4.1@2251.5,5638 ; 2311.4,302.1 T14.2@2251.5,362 ; 2311.4,421.9 T14.2@2251.5,362 ; 2311.4,578.1 T14.1@2251.5,638 ; 2311.4,697.9 T14.1@2251.5,638 ; 2311.4,5302.1 T4.2@2251.5,5362 ; 2311.4,5421.9 T4.2@2251.5,5362 ; 2311.4,5578.1 T4.1@2251.5,5638 ; 2311.4,5697.9 T4.1@2251.5,5638 ; 2388.6,302.1 T14.3@2448.5,362 ; 2388.6,421.9 T14.3@2448.5,362 ; 2388.6,578.1 T14.4@2448.5,638 ; 2388.6,697.9 T14.4@2448.5,638 ; 2388.6,5302.1 T4.3@2448.5,5362 ; 2388.6,5421.9 T4.3@2448.5,5362 ; 2388.6,5578.1 T4.4@2448.5,5638 ; 2388.6,5697.9 T4.4@2448.5,5638 ; 2508.4,302.1 T14.3@2448.5,362 ; 2508.4,421.9 T14.3@2448.5,362 ; 2508.4,578.1 T14.4@2448.5,638 ; 2508.4,697.9 T14.4@2448.5,638 ; 2508.4,5302.1 T4.3@2448.5,5362 ; 2508.4,5421.9 T4.3@2448.5,5362 ; 2508.4,5578.1 T4.4@2448.5,5638 ; 2508.4,5697.9 T4.4@2448.5,5638 ; 4004.3,454.3 J6.2@4050,500 ; 4004.3,545.7 J6.2@4050,500 ; 4004.3,5454.3 J3.2@4050,5500 ; 4004.3,5545.7 J3.2@4050,5500 ; 4095.7,454.3 J6.2@4050,500 ; 4095.7,545.7 J6.2@4050,500 ; 4095.7,5454.3 J3.2@4050,5500 ; 4095.7,5545.7 J3.2@4050,5500 ; 4191.6,302.1 T10.2@4251.5,362 ; 4191.6,421.9 T10.2@4251.5,362 ; 4191.6,578.1 T10.1@4251.5,638 ; 4191.6,697.9 T10.1@4251.5,638 ; 4191.6,5302.1 T6.2@4251.5,5362 ; 4191.6,5421.9 T6.2@4251.5,5362 ; 4191.6,5578.1 T6.1@4251.5,5638 ; 4191.6,5697.9 T6.1@4251.5,5638 ; 4311.4,302.1 T10.2@4251.5,362 ; 4311.4,421.9 T10.2@4251.5,362 ; 4311.4,578.1 T10.1@4251.5,638 ; 4311.4,697.9 T10.1@4251.5,638 ; 4311.4,5302.1 T6.2@4251.5,5362 ; 4311.4,5421.9 T6.2@4251.5,5362 ; 4311.4,5578.1 T6.1@4251.5,5638 ; 4311.4,5697.9 T6.1@4251.5,5638 ; 4388.6,302.1 T10.3@4448.5,362 ; 4388.6,421.9 T10.3@4448.5,362 ; 4388.6,578.1 T10.4@4448.5,638 ; 4388.6,697.9 T10.4@4448.5,638 ; 4388.6,5302.1 T6.3@4448.5,5362 ; 4388.6,5421.9 T6.3@4448.5,5362 ; 4388.6,5578.1 T6.4@4448.5,5638 ; 4388.6,5697.9 T6.4@4448.5,5638 ; 4508.4,302.1 T10.3@4448.5,362 ; 4508.4,421.9 T10.3@4448.5,362 ; 4508.4,578.1 T10.4@4448.5,638 ; 4508.4,697.9 T10.4@4448.5,638 ; 4508.4,5302.1 T6.3@4448.5,5362 ; 4508.4,5421.9 T6.3@4448.5,5362 ; 4508.4,5578.1 T6.4@4448.5,5638 ; 4508.4,5697.9 T6.4@4448.5,5638 ; 6004.3,454.3 J7.2@6050,500 ; 6004.3,545.7 J7.2@6050,500 ; 6004.3,5454.3 J4.2@6050,5500 ; 6004.3,5545.7 J4.2@6050,5500 ; 6095.7,454.3 J7.2@6050,500 ; 6095.7,545.7 J7.2@6050,500 ; 6095.7,5454.3 J4.2@6050,5500 ; 6095.7,5545.7 J4.2@6050,5500 ; 6191.6,302.1 T12.2@6251.5,362 ; 6191.6,421.9 T12.2@6251.5,362 ; 6191.6,578.1 T12.1@6251.5,638 ; 6191.6,697.9 T12.1@6251.5,638 ; 6191.6,5302.1 T8.2@6251.5,5362 ; 6191.6,5421.9 T8.2@6251.5,5362 ; 6191.6,5578.1 T8.1@6251.5,5638 ; 6191.6,5697.9 T8.1@6251.5,5638 ; 6311.4,302.1 T12.2@6251.5,362 ; 6311.4,421.9 T12.2@6251.5,362 ; 6311.4,578.1 T12.1@6251.5,638 ; 6311.4,697.9 T12.1@6251.5,638 ; 6311.4,5302.1 T8.2@6251.5,5362 ; 6311.4,5421.9 T8.2@6251.5,5362 ; 6311.4,5578.1 T8.1@6251.5,5638 ; 6311.4,5697.9 T8.1@6251.5,5638 ; 6388.6,302.1 T12.3@6448.5,362 ; 6388.6,421.9 T12.3@6448.5,362 ; 6388.6,578.1 T12.4@6448.5,638 ; 6388.6,697.9 T12.4@6448.5,638 ; 6388.6,5302.1 T8.3@6448.5,5362 ; 6388.6,5421.9 T8.3@6448.5,5362 ; 6388.6,5578.1 T8.4@6448.5,5638 ; 6388.6,5697.9 T8.4@6448.5,5638 ; 6508.4,302.1 T12.3@6448.5,362 ; 6508.4,421.9 T12.3@6448.5,362 ; 6508.4,578.1 T12.4@6448.5,638 ; 6508.4,697.9 T12.4@6448.5,638 ; 6508.4,5302.1 T8.3@6448.5,5362 ; 6508.4,5421.9 T8.3@6448.5,5362 ; 6508.4,5578.1 T8.4@6448.5,5638 ; 6508.4,5697.9 T8.4@6448.5,5638 ; 7491.6,5302.1 T18.2@7551.5,5362 ; 7491.6,5421.9 T18.2@7551.5,5362 ; 7491.6,5578.1 T18.1@7551.5,5638 ; 7491.6,5697.9 T18.1@7551.5,5638 ; 7611.4,5302.1 T18.2@7551.5,5362 ; 7611.4,5421.9 T18.2@7551.5,5362 ; 7611.4,5578.1 T18.1@7551.5,5638 ; 7611.4,5697.9 T18.1@7551.5,5638 ; 7688.6,5302.1 T18.3@7748.5,5362 ; 7688.6,5421.9 T18.3@7748.5,5362 ; 7688.6,5578.1 T18.4@7748.5,5638 ; 7688.6,5697.9 T18.4@7748.5,5638 ; 7808.4,5302.1 T18.3@7748.5,5362 ; 7808.4,5421.9 T18.3@7748.5,5362 ; 7808.4,5578.1 T18.4@7748.5,5638 ; 7808.4,5697.9 T18.4@7748.5,5638 ; 7904.3,5454.3 J9.2@7950,5500 ; 7904.3,5545.7 J9.2@7950,5500 ; 7995.7,5454.3 J9.2@7950,5500 ; 7995.7,5545.7 J9.2@7950,5500 ; 8004.3,454.3 J8.2@8050,500 ; 8004.3,545.7 J8.2@8050,500 ; 8095.7,454.3 J8.2@8050,500 ; 8095.7,545.7 J8.2@8050,500 ; 8191.6,302.1 T16.2@8251.5,362 ; 8191.6,421.9 T16.2@8251.5,362 ; 8191.6,578.1 T16.1@8251.5,638 ; 8191.6,697.9 T16.1@8251.5,638 ; 8311.4,302.1 T16.2@8251.5,362 ; 8311.4,421.9 T16.2@8251.5,362 ; 8311.4,578.1 T16.1@8251.5,638 ; 8311.4,697.9 T16.1@8251.5,638 ; 8388.6,302.1 T16.3@8448.5,362 ; 8388.6,421.9 T16.3@8448.5,362 ; 8388.6,578.1 T16.4@8448.5,638 ; 8388.6,697.9 T16.4@8448.5,638 ; 8508.4,302.1 T16.3@8448.5,362 ; 8508.4,421.9 T16.3@8448.5,362 ; 8508.4,578.1 T16.4@8448.5,638 ; 8508.4,697.9 T16.4@8448.5,638 ; 10524.3,774.3 J11.3@10570,820 ; 10524.3,865.7 J11.3@10570,820 ; 10529.3,1270.7 J21.2@10575,1225 ; 10615.7,774.3 J11.3@10570,820 ; 10615.7,865.7 J11.3@10570,820 ; 10620.7,1179.3 J21.2@10575,1225 ; 10620.7,1270.7 J21.2@10575,1225
  other v1: 9100,400 9700,400 10442,711 8400,900 9100,900 600,1000 2600,1000 6600,1000 4600,1100 8400,1300 9100,1300 700,1600 2600,1600 6600,1600 8166,1690 8189,1690 8212,1690 4600,1700 8166,1713 8189,1713 8212,1713 8166,1736 8189,1736 8212,1736 8166,1759 8189,1759 8212,1759 8166,1782 8189,1782 8212,1782 9350,1800 9400,1800 8166,1805 8189,1805 8212,1805 1843,1826 1881,1826 1919,1826 3843,1826 3881,1826 3919,1826 5843,1826 5881,1826 5919,1826 8166,1828 8189,1828 8212,1828 2187,1830 2227,1830 4187,1830 4227,1830 6187,1830 6227,1830 9350,1850 9400,1850 8166,1851 8189,1851 8212,1851 2187,1865 2227,1865 4187,1865 4227,1865 6187,1865 6227,1865 1840,1885 1875,1885 3840,1885 3875,1885 5840,1885 5875,1885 2187,1900 2227,1900 4187,1900 4227,1900 6187,1900 6227,1900 9350,1900 9400,1900 9350,1950 9400,1950 9375,2000 2187,2080 2227,2080 4187,2080 4227,2080 6187,2080 6227,2080 2600,2100 4600,2100 6600,2100 1830,2115 1870,2115 2187,2115 2227,2115 3830,2115 3870,2115 4187,2115 4227,2115 5830,2115 5870,2115 6187,2115 6227,2115 1840,2150 1885,2150 2187,2150 2227,2150 3840,2150 3885,2150 4187,2150 4227,2150 5840,2150 5885,2150 6187,2150 6227,2150 8092,2177 8127,2177 1895,2185 1935,2185 3895,2185 3935,2185 5895,2185 5935,2185 8092,2212 8127,2212 8092,2247 8127,2247 8092,2282 8127,2282 9200,3600 10000,3600 7873,3718 7908,3718 7873,3753 7908,3753 7873,3788 7908,3788 2119,3799 2159,3799 4119,3799 4159,3799 6119,3799 6159,3799 7873,3823 7908,3823 2119,3834 2159,3834 4119,3834 4159,3834 6119,3834 6159,3834 1772,3850 1812,3850 3772,3850 3812,3850 5772,3850 5812,3850 2119,3869 2159,3869 4119,3869 4159,3869 6119,3869 6159,3869 1772,3885 1812,3885 3772,3885 3812,3885 5772,3885 5812,3885 1772,3920 1812,3920 3772,3920 3812,3920 5772,3920 5812,3920 300,4000 1500,4000 1772,4100 1812,4100 3772,4100 3812,4100 5772,4100 5812,4100 2124,4115 2159,4115 4124,4115 4159,4115 6124,4115 6159,4115 1772,4135 1812,4135 3772,4135 3812,4135 5772,4135 5812,4135 7788,4149 7811,4149 7834,4149 1772,4170 1812,4170 3772,4170 3812,4170 5772,4170 5812,4170 7788,4172 7811,4172 7834,4172 2080,4174 2118,4174 2156,4174 4080,4174 4118,4174 4156,4174 6080,4174 6118,4174 6156,4174 7788,4195 7811,4195 7834,4195 2700,4200 4600,4200 6400,4200 6800,4200 7788,4218 7811,4218 7834,4218 7788,4241 7811,4241 7834,4241 7788,4264 7811,4264 7834,4264 7788,4287 7811,4287 7834,4287 7788,4310 7811,4310 7834,4310 700,4400 6400,4600 6800,4600 7100,4600 7500,4600 700,4800 6400,4900 6800,4900 7100,4900 7500,4900 9100,4900 9700,4900 2700,5100 4600,5100 700,5200 6800,5300 7100,5300 9100,5300 9700,5300 700,5600 6800,5700 7100,5700 9100,5700 9700,5700 10200,5700
  other v2: 2105,1960 4105,1960 6105,1960 8038,1960 8051,1960 8061,1960 8048,1971 8060,1971 1988.2,1976.4 2011.8,1976.4 3988.2,1976.4 4011.8,1976.4 5988.2,1976.4 6011.8,1976.4 8038,1982 8051,1982 8061,1983 1976.4,1988.2 2000,1988.2 2023.6,1988.2 3976.4,1988.2 4000,1988.2 4023.6,1988.2 5976.4,1988.2 6000,1988.2 6023.6,1988.2 1976.4,2007.9 2000,2007.9 3976.4,2007.9 4000,2007.9 5976.4,2007.9 6000,2007.9 7991,2012 8009,2013 8026,2013 8043,2013 8061,2013 1988.2,2017.7 3988.2,2017.7 5988.2,2017.7 8000,2024 8018,2024 8035,2024 8052,2025 1976.4,2027.6 2000,2027.6 3976.4,2027.6 4000,2027.6 5976.4,2027.6 6000,2027.6 7991,2034 8009,2034 8027.6,2033.5 8044,2034 8061,2034 8000,2044 8018,2044 8035,2044 8052,2045 7991,2055 8008,2055 8026,2055 8044,2055 8061,2055 8050,2082 8039,2088 8062,2088 7938,3912 7961,3912 7950,3918 7939,3945 7956,3945 7974,3945 7992,3945 8009,3945 7948,3955 7965,3956 7982,3956 8000,3956 7939,3966 7956,3966 7972.4,3966.5 7991,3966 8009,3966 2000,3972.4 2023.6,3972.4 4000,3972.4 4023.6,3972.4 6000,3972.4 6023.6,3972.4 7948,3975 7965,3976 7982,3976 8000,3976 2011.8,3982.3 4011.8,3982.3 6011.8,3982.3 7939,3987 7957,3987 7974,3987 7991,3987 8009,3988 2000,3992.1 2023.6,3992.1 4000,3992.1 4023.6,3992.1 6000,3992.1 6023.6,3992.1 1976.4,4011.8 2000,4011.8 2023.6,4011.8 3976.4,4011.8 4000,4011.8 4023.6,4011.8 5976.4,4011.8 6000,4011.8 6023.6,4011.8 7939,4017 7949,4018 7962,4018 1988.2,4023.6 2011.8,4023.6 3988.2,4023.6 4011.8,4023.6 5988.2,4023.6 6011.8,4023.6 7940,4029 7952,4029 1895,4040 3895,4040 5895,4040 7939,4040 7949,4040 7962,4040
  other v3: 1988.2,1976.4 2011.8,1976.4 3988.2,1976.4 4011.8,1976.4 5988.2,1976.4 6011.8,1976.4 1976.4,1988.2 2000,1988.2 2023.6,1988.2 3976.4,1988.2 4000,1988.2 4023.6,1988.2 5976.4,1988.2 6000,1988.2 6023.6,1988.2 1976.4,2007.9 2000,2007.9 3976.4,2007.9 4000,2007.9 5976.4,2007.9 6000,2007.9 1988.2,2017.7 3988.2,2017.7 5988.2,2017.7 1976.4,2027.6 2000,2027.6 3976.4,2027.6 4000,2027.6 5976.4,2027.6 6000,2027.6 2000,3972.4 2023.6,3972.4 4000,3972.4 4023.6,3972.4 6000,3972.4 6023.6,3972.4 2011.8,3982.3 4011.8,3982.3 6011.8,3982.3 2000,3992.1 2023.6,3992.1 4000,3992.1 4023.6,3992.1 6000,3992.1 6023.6,3992.1 1976.4,4011.8 2000,4011.8 2023.6,4011.8 3976.4,4011.8 4000,4011.8 4023.6,4011.8 5976.4,4011.8 6000,4011.8 6023.6,4011.8 1988.2,4023.6 2011.8,4023.6 3988.2,4023.6 4011.8,4023.6 5988.2,4023.6 6011.8,4023.6
PGOOD1: J13.19 R56.1 U1.2 U10.3 U11.10 | length 9625.6
  TopLayer w9: v1(9540,2790) 9612,2790 9740.7,2918.7 U11.10@9740.7,2950.3
  TopLayer w12: U1.2@2053.1,3967.5 2081.5,3967.5 2087,3962 2121,3962 v1(2156,3927) ; v1(9082.7,2790) 9188.7,2896 9434,2896 v1(9540,2790)
  MidLayer2 w12: v1(2156,3927) 2249,3834 2469.1,3834 3189.1,3114 8611,3114 8906,2819 9053.7,2819 v1(9082.7,2790) ; v1(9540,2790) 9651,2679 10371,2679 J13.19@10500,2550
  BottomLayer w12: R56.1@9047.7,2790 v1(9082.7,2790) 9135,2842.3 9135,2897 9148.4,2910.4 U10.3@9183.9,2910.4
PGOOD2: J13.17 R57.1 U2.2 U10.4 U11.9 | length 7687.9
  TopLayer w9: v1(9540,2850) 9646,2850 9725,2929 U11.9@9725,2950.3
  TopLayer w12: U2.2@4053.1,3967.5 4081.5,3967.5 4086,3963 4125,3963 v1(4149,3939) ; v1(9082.7,2850) 9151.7,2919 9471,2919 v1(9540,2850)
  MidLayer2 w12: v1(4149,3939) 4149,3934 4234,3849 4868,3849 5403,3314 8975,3314 9005,3284 9005,2927.7 v1(9082.7,2850) ; v1(9540,2850) 9680,2710 10440,2710 J13.17@10500,2650
  BottomLayer w12: R57.1@9047.7,2850 v1(9082.7,2850) 9112,2879.3 9112,2906 9142,2936 U10.4@9183.9,2936
PGOOD3: J13.15 R58.2 U3.2 U10.5 U11.8 | length 5548.6
  TopLayer w9: v1(9540,2910) 9678,2910 9709.3,2941.3 U11.8@9709.3,2950.3
  TopLayer w12: U3.2@6053.1,3967.5 6081.5,3967.5 6084,3965 6118,3965 v1(6156,3927) ; v1(9082.7,2910) 9116.7,2944 9506,2944 v1(9540,2910)
  MidLayer2 w12: v1(6156,3927) 6241,3842 6899,3842 7250,3491 8878,3491 9028,3341 9028,2964.7 v1(9082.7,2910) ; v1(9540,2910) 9625,2825 10008,2825 10048,2785 10465,2785 J13.15@10500,2750
  BottomLayer w12: R58.2@9047.7,2910 v1(9082.7,2910) 9134.3,2961.6 U10.5@9183.9,2961.6
PGOOD4: J13.13 R59.1 U4.2 U10.6 U11.7 | length 9697.1
  TopLayer w9: v1(9540,2970) 9557.2,2952.8 U11.7@9689.3,2952.8
  TopLayer w12: v1(1868,2072) 1868,2053 1879.9,2041.1 1909.9,2041.1 1918.5,2032.5 U4.2@1946.9,2032.5 ; v1(9082.7,2970) v1(9540,2970)
  MidLayer2 w12: v1(1868,2072) 1869,2072 2604,2807 8391,2807 8481,2717 9063,2717 9117,2771 9117,2926.5 v1(9082.7,2970) ; v1(9540,2970) 9624,2886 9970,2886 10001,2855 10495,2855 J13.13@10500,2850
  BottomLayer w12: R59.1@9047.7,2970 v1(9082.7,2970) 9099.9,2987.2 U10.6@9183.9,2987.2
PGOOD5: J13.9 R60.1 U5.2 U10.7 U11.6 | length 7820.6
  TopLayer w9: v1(9540,3030) 9601.5,2968.5 U11.6@9689.3,2968.5
  TopLayer w12: v1(3868,2072) 3868,2053 3878,2043 3908,2043 3918.5,2032.5 U5.2@3946.9,2032.5 ; v1(9082.7,3030) v1(9540,3030)
  MidLayer2 w12: v1(3868,2072) 3871,2072 4416,2617 8241,2617 8273,2585 9015,2585 9156,2726 9156,3008 9134,3030 v1(9082.7,3030) ; v1(9540,3030) 9565,3005 10455,3005 J13.9@10500,3050
  BottomLayer w12: R60.1@9047.7,3030 v1(9082.7,3030) 9099.9,3012.8 U10.7@9183.9,3012.8
PGOOD6: J13.7 R61.1 U6.2 U10.8 U11.5 | length 6182.3
  TopLayer w9: v1(9540,3090) 9579,3051 9579,3041 9635.7,2984.3 U11.5@9695,2984.3
  TopLayer w12: v1(5868,2072) 5868,2053 5879.9,2041.1 5909.9,2041.1 5918.5,2032.5 U6.2@5946.9,2032.5 ; v1(9082.7,3090) v1(9540,3090)
  MidLayer2 w12: v1(5868,2072) 5871,2072 6239,2440 8170,2440 8186,2424 9081,2424 9280,2623 9280,3011 9201,3090 v1(9082.7,3090) ; v1(9540,3090) 9576,3126 9928,3126 9952,3150 J13.7@10500,3150
  BottomLayer w12: R61.1@9047.7,3090 v1(9082.7,3090) 9134.3,3038.4 U10.8@9183.9,3038.4
PGOOD7: J13.5 R62.2 U7.9 U10.9 U11.4 | length 4240.9
  TopLayer w9: v1(9540,3150) 9610,3080 9610,3041 9651,3000 U11.4@9695,3000
  TopLayer w12: v1(7698,4060) 7729,4091 7842.6,4091 7848,4085.6 U7.9@7897.6,4085.6 ; v1(9082.7,3150) 9105.7,3173 9517,3173 v1(9540,3150)
  MidLayer2 w12: v1(7698,4060) 7637,3999 7637,3802 7782,3657 8786,3657 9051,3392 9051,3181.7 v1(9082.7,3150) ; v1(9540,3150) 9576,3186 9928,3186 9969,3227 10477,3227 J13.5@10500,3250
  BottomLayer w12: R62.2@9047.7,3150 v1(9082.7,3150) 9113,3119.7 9113,3095 9144,3064 U10.9@9183.9,3064
PGOOD8: J13.3 R63.1 U8.9 U10.10 U11.3 | length 4608.1
  TopLayer w9: v1(9540,3210) 9642,3108 9642,3038 9664.3,3015.7 U11.3@9698.9,3015.7
  TopLayer w12: U8.9@8102.4,1914.4 8140.6,1914.4 8155,1900 v1(8253,1900) ; v1(9082.7,3210) v1(9540,3210)
  MidLayer2 w12: v1(8362,2125) 8362,2189 8478,2305 9141,2305 9438,2602 9438,3067 9397,3108 9340,3108 9263,3185 9107.7,3185 v1(9082.7,3210) ; v1(9540,3210) 9628,3298 10448,3298 J13.3@10500,3350
  BottomLayer w12: v1(8253,1900) 8282,1900 8362,1980 v1(8362,2125) ; R63.1@9047.7,3210 v1(9082.7,3210) 9135,3157.7 9135,3103 9148.4,3089.6 U10.10@9183.9,3089.6
PVIN: C1.2 C2.2 C7.2 C8.2 C13.2 C14.2 C19.2 C20.2 C25.2 C26.2 C27.2 C28.2 C38.2 C39.2 C40.2 C41.2 C101.1 C110.2 C111.2 C112.2 C113.2 C125.2 C138.1 D15.2 J1.1 J18.1 R1.2 R4.2 R7.2 R10.2 R21.2 R22.2 R27.1 R45.1 T1.1 T1.2 T1.3 T1.4 U1.12 U1.13 U1.14 U1.17 U2.12 U2.13 U2.14 U2.17 U3.12 U3.13 U3.14 U3.17 U4.12 U4.13 U4.14 U4.17 U5.12 U5.13 U5.14 U5.17 U6.12 U6.13 U6.14 U6.17 U7.18 U7.19 U8.18 U8.19 U9.3 V1.2 | length 1783.6
  TopLayer w32: 331.6,3282.1 T1.2@391.5,3342 ; 331.6,3401.9 T1.2@391.5,3342 ; 331.6,3558.1 T1.1@391.5,3618 ; 331.6,3677.9 T1.1@391.5,3618 ; 432.4,3232.6 J1.1@490,3175 547.6,3232.6 ; 451.4,3282.1 T1.2@391.5,3342 ; 451.4,3401.9 T1.2@391.5,3342 ; 451.4,3558.1 T1.1@391.5,3618 ; 451.4,3677.9 T1.1@391.5,3618 ; 506.6,2080 J18.1@576.7,2080 ; 528.6,3282.1 T1.3@588.5,3342 ; 528.6,3401.9 T1.3@588.5,3342 ; 528.6,3558.1 T1.4@588.5,3618 ; 528.6,3677.9 T1.4@588.5,3618 ; 576.7,2205.1 J18.1@576.7,2080 ; 646.8,2080 J18.1@576.7,2080 ; 648.4,3282.1 T1.3@588.5,3342 ; 648.4,3401.9 T1.3@588.5,3342 ; 648.4,3558.1 T1.4@588.5,3618 ; 648.4,3677.9 T1.4@588.5,3618
  other v1: 9150,1880 9200,1905 9150,1940 9200,1970 9150,2005 9200,2035 9150,2065 7889,2177 7924,2177 7889,2212 7924,2212 7889,2247 7924,2247 7889,2282 7924,2282 8076,3718 8111,3718 8076,3753 8111,3753 8076,3788 8111,3788 8076,3823 8111,3823
  other v2: 7936,2012 7959,2012 7948,2022 7936,2029 7959,2029 2031.5,2035.4 2044,2035 2059,2035 4031.5,2035.4 4044,2035 4059,2035 6031.5,2035.4 6044,2035 6059,2035 7948,2039 7936,2049 7959,2049 2031.5,2051.2 2044,2051 4031.5,2051.2 4044,2051 6031.5,2051.2 6044,2051 7948,2056 2030,2068 2044,2068 4030,2068 4044,2068 6030,2068 6044,2068 7947,2082 2030,2085 2044,2085 4030,2085 4044,2085 6030,2085 6044,2085 7936,2089 7960,2089 8040,3911 8064,3911 1956,3915 1970,3915 3956,3915 3970,3915 5956,3915 5970,3915 8053,3918 1956,3932 1970,3932 3956,3932 3970,3932 5956,3932 5970,3932 8052,3944 1956,3949 1968.5,3948.8 3956,3949 3968.5,3948.8 5956,3949 5968.5,3948.8 8041,3951 8064,3951 8052,3961 1941,3965 1956,3965 1968.5,3964.6 3941,3965 3956,3965 3968.5,3964.6 5941,3965 5956,3965 5968.5,3964.6 8041,3971 8064,3971 8052,3978 8041,3988 8064,3988
SALERT7: J17.2 R31.1 U7.14 | length 533
  TopLayer w12: J17.2@7490,3880 7529,3919 7789,3919 7812.9,3942.9 U7.14@7897.6,3942.9
  BottomLayer w12: R31.1@7392.7,3875 7485,3875 J17.2@7490,3880
SALERT8: J14.2 R46.1 U8.14 | length 756.6
  TopLayer w12: U8.14@8102.4,2057.1 8122.1,2057.1 8126,2061 8253,2061 8263,2071 8325,2071 8350,2046 8350,1885 J14.2@8520,1715
  BottomLayer w12: J14.2@8520,1715 8530,1725 R46.1@8607.3,1725
SCL: J11.1 R48.1 U1.4 U2.4 U3.4 U4.4 U5.4 U6.4 U7.13 U8.13 | length 19390.2
  TopLayer w12: v1(1724,1975) 1751,2002 1888,2002 1900.8,1989.2 U4.4@1946.9,1989.2 ; U1.4@2053.1,4010.8 2097.2,4010.8 2108,4000 v1(2192,4000) ; v1(3724,1975) 3751,2002 3888,2002 3900.8,1989.2 U5.4@3946.9,1989.2 ; U2.4@4053.1,4010.8 4099.2,4010.8 4110,4000 v1(4195,4000) ; v1(5724,1975) 5751,2002 5888,2002 5900.8,1989.2 U6.4@5946.9,1989.2 ; U3.4@6053.1,4010.8 6098.2,4010.8 6108,4001 v1(6194,4001) ; v1(7672,3951) 7788,3951 7808.5,3971.5 U7.13@7897.6,3971.5 ; U8.13@8102.4,2028.5 8239.5,2028.5 v1(8241,2030) ; J11.1@10570,620 R48.1@10682.3,620
  MidLayer2 w12: v1(2387,3037) v1(4409,3037) 6407,3037 v1(6409,3035) v1(7807,3035) ; v1(8241,2030) 8312,1959 8852,1959 9444,1367 9665,1367 10412,620 J11.1@10570,620
  BottomLayer w12: v1(1724,1975) 1724,2291 2387,2954 v1(2387,3037) 2387,3883 2270,4000 v1(2192,4000) ; v1(3724,1975) 3724,2270 4409,2955 v1(4409,3037) 4409,3786 v1(4195,4000) ; v1(5724,1975) 5724,2253 6409,2938 v1(6409,3035) 6409,3786 v1(6194,4001) ; v1(7672,3951) 7625,3904 7625,3217 v1(7807,3035) 8241,2601 v1(8241,2030)
SDA: J11.2 R47.1 U1.1 U2.1 U3.1 U4.1 U5.1 U6.1 U7.12 U8.12 | length 19042.5
  TopLayer w12: v1(1912,2071) 1928.9,2054.1 U4.1@1946.9,2054.1 ; U1.1@2053.1,3945.9 2081.1,3945.9 v1(2100,3927) ; v1(3912,2071) 3928.9,2054.1 U5.1@3946.9,2054.1 ; U2.1@4053.1,3945.9 4083.1,3945.9 v1(4102,3927) ; v1(5912,2071) 5928.9,2054.1 U6.1@5946.9,2054.1 ; U3.1@6053.1,3945.9 6088.1,3945.9 v1(6106,3928) ; v1(7736,3986) 7750,4000 U7.12@7897.6,4000 ; U8.12@8102.4,2000 8275,2000 v1(8306,2031) ; J11.2@10570,720 R47.1@10682.3,720
  MidLayer2 w12: v1(1672,2071) 1784,2071 1814,2041 1882,2041 v1(1912,2071) ; v1(2267,2963) v1(4277,2963) v1(6231,2963) v1(8054,2963) ; v1(3672,2071) 3784,2071 3814,2041 3882,2041 v1(3912,2071) ; v1(5672,2071) 5784,2071 5814,2041 5882,2041 v1(5912,2071) ; v1(8306,2031) 8900,2031 9341,1590 9700,1590 J11.2@10570,720
  BottomLayer w12: v1(1672,2071) 1672,2368 v1(2267,2963) 2267,3913 2215,3965 2138,3965 v1(2100,3927) ; v1(3672,2071) 3672,2353 4277,2958 v1(4277,2963) 4278,2964 4278,3801 4173,3906 4123,3906 v1(4102,3927) ; v1(5672,2071) 5672,2404 v1(6231,2963) 6231,3848 6181,3898 6136,3898 v1(6106,3928) ; v1(7736,3986) 7736,3282 8054,2964 v1(8054,2963) 8055,2963 8306,2712 v1(8306,2031)
SYNC7: J17.1 R54.1 U7.11 | length 527.1
  TopLayer w12: J17.1@7490,3980 7538.5,4028.5 U7.11@7897.6,4028.5
  BottomLayer w12: R54.1@7392.7,3975 7485,3975 J17.1@7490,3980
SYNC8: J14.1 R38.1 U8.11 | length 717.6
  TopLayer w12: U8.11@8102.4,1971.5 8144.5,1971.5 8146,1970 8269,1970 8318,1921 8318,1817 J14.1@8520,1615
  BottomLayer w12: J14.1@8520,1615 8530,1625 R38.1@8607.3,1625
VCC3: C133.2 U3.10 | length 75.4
  TopLayer w12: v2(5900,4010.8) U3.10@5946.9,4010.8
  BottomLayer w12: v2(5900,4010.8) 5908.5,4002.3 C133.2@5925,4002.3
VOUT1: C4.1 C5.1 C102.2 C139.1 C140.1 J2.1 T3.1 T3.2 T3.3 T3.4 U1.5 U1.7 | length 4437.4
  TopLayer w12: U1.5@2053.1,4032.5 2115.5,4032.5 v1(2121,4027)
  TopLayer w20: J2.1@1950,5500 1968.5,5481.5 C102.2@1968.5,5360
  TopLayer w32: 1491.6,5302.1 T3.2@1551.5,5362 ; 1491.6,5421.9 T3.2@1551.5,5362 ; 1491.6,5578.1 T3.1@1551.5,5638 ; 1491.6,5697.9 T3.1@1551.5,5638 ; 1611.4,5302.1 T3.2@1551.5,5362 ; 1611.4,5421.9 T3.2@1551.5,5362 ; 1611.4,5578.1 T3.1@1551.5,5638 ; 1611.4,5697.9 T3.1@1551.5,5638 ; 1688.6,5302.1 T3.3@1748.5,5362 ; 1688.6,5421.9 T3.3@1748.5,5362 ; 1688.6,5578.1 T3.4@1748.5,5638 ; 1688.6,5697.9 T3.4@1748.5,5638 ; 1808.4,5302.1 T3.3@1748.5,5362 ; 1808.4,5421.9 T3.3@1748.5,5362 ; 1808.4,5578.1 T3.4@1748.5,5638 ; 1808.4,5697.9 T3.4@1748.5,5638
  MidLayer2 w12: J2.1@1950,5500 1950,5399 2024,5325 v1(2024,4209) ; v1(2024,4174) 2024,4124 v1(2121,4027)
  BottomLayer w32: 1491.6,5302.1 T3.2@1551.5,5362 ; 1491.6,5421.9 T3.2@1551.5,5362 ; 1491.6,5578.1 T3.1@1551.5,5638 ; 1491.6,5697.9 T3.1@1551.5,5638 ; 1611.4,5302.1 T3.2@1551.5,5362 ; 1611.4,5421.9 T3.2@1551.5,5362 ; 1611.4,5578.1 T3.1@1551.5,5638 ; 1611.4,5697.9 T3.1@1551.5,5638 ; 1688.6,5302.1 T3.3@1748.5,5362 ; 1688.6,5421.9 T3.3@1748.5,5362 ; 1688.6,5578.1 T3.4@1748.5,5638 ; 1688.6,5697.9 T3.4@1748.5,5638 ; 1808.4,5302.1 T3.3@1748.5,5362 ; 1808.4,5421.9 T3.3@1748.5,5362 ; 1808.4,5578.1 T3.4@1748.5,5638 ; 1808.4,5697.9 T3.4@1748.5,5638
  other v1: 1944,4174 1984,4174 1944,4209 1984,4209
  other v2: 1979,4052 2000,4052.2 2021,4052
VOUT2: C10.1 C11.1 C103.2 C141.1 C142.1 J3.1 T5.1 T5.2 T5.3 T5.4 U2.5 U2.7 | length 4437.4
  TopLayer w12: U2.5@4053.1,4032.5 4115.5,4032.5 v1(4121,4027)
  TopLayer w25: J3.1@3950,5500 3968.5,5481.5 C103.2@3968.5,5360
  TopLayer w32: 3491.6,5302.1 T5.2@3551.5,5362 ; 3491.6,5421.9 T5.2@3551.5,5362 ; 3491.6,5578.1 T5.1@3551.5,5638 ; 3491.6,5697.9 T5.1@3551.5,5638 ; 3611.4,5302.1 T5.2@3551.5,5362 ; 3611.4,5421.9 T5.2@3551.5,5362 ; 3611.4,5578.1 T5.1@3551.5,5638 ; 3611.4,5697.9 T5.1@3551.5,5638 ; 3688.6,5302.1 T5.3@3748.5,5362 ; 3688.6,5421.9 T5.3@3748.5,5362 ; 3688.6,5578.1 T5.4@3748.5,5638 ; 3688.6,5697.9 T5.4@3748.5,5638 ; 3808.4,5302.1 T5.3@3748.5,5362 ; 3808.4,5421.9 T5.3@3748.5,5362 ; 3808.4,5578.1 T5.4@3748.5,5638 ; 3808.4,5697.9 T5.4@3748.5,5638
  MidLayer2 w12: J3.1@3950,5500 3950,5408 4024,5334 v1(4024,4209) ; v1(4024,4174) 4024,4124 v1(4121,4027)
  BottomLayer w32: 3491.6,5302.1 T5.2@3551.5,5362 ; 3491.6,5421.9 T5.2@3551.5,5362 ; 3491.6,5578.1 T5.1@3551.5,5638 ; 3491.6,5697.9 T5.1@3551.5,5638 ; 3611.4,5302.1 T5.2@3551.5,5362 ; 3611.4,5421.9 T5.2@3551.5,5362 ; 3611.4,5578.1 T5.1@3551.5,5638 ; 3611.4,5697.9 T5.1@3551.5,5638 ; 3688.6,5302.1 T5.3@3748.5,5362 ; 3688.6,5421.9 T5.3@3748.5,5362 ; 3688.6,5578.1 T5.4@3748.5,5638 ; 3688.6,5697.9 T5.4@3748.5,5638 ; 3808.4,5302.1 T5.3@3748.5,5362 ; 3808.4,5421.9 T5.3@3748.5,5362 ; 3808.4,5578.1 T5.4@3748.5,5638 ; 3808.4,5697.9 T5.4@3748.5,5638
  other v1: 3944,4174 3984,4174 3944,4209 3984,4209
  other v2: 3979,4052 4000,4052.2 4021,4052
VOUT3: C16.1 C17.1 C104.2 C143.1 C144.1 J4.1 T7.1 T7.2 T7.3 T7.4 U3.5 U3.7 | length 4437.4
  TopLayer w12: U3.5@6053.1,4032.5 6115.5,4032.5 v1(6121,4027)
  TopLayer w20: J4.1@5950,5500 5968.5,5481.5 C104.2@5968.5,5360
  TopLayer w32: 5491.6,5302.1 T7.2@5551.5,5362 ; 5491.6,5421.9 T7.2@5551.5,5362 ; 5491.6,5578.1 T7.1@5551.5,5638 ; 5491.6,5697.9 T7.1@5551.5,5638 ; 5611.4,5302.1 T7.2@5551.5,5362 ; 5611.4,5421.9 T7.2@5551.5,5362 ; 5611.4,5578.1 T7.1@5551.5,5638 ; 5611.4,5697.9 T7.1@5551.5,5638 ; 5688.6,5302.1 T7.3@5748.5,5362 ; 5688.6,5421.9 T7.3@5748.5,5362 ; 5688.6,5578.1 T7.4@5748.5,5638 ; 5688.6,5697.9 T7.4@5748.5,5638 ; 5808.4,5302.1 T7.3@5748.5,5362 ; 5808.4,5421.9 T7.3@5748.5,5362 ; 5808.4,5578.1 T7.4@5748.5,5638 ; 5808.4,5697.9 T7.4@5748.5,5638
  MidLayer2 w12: J4.1@5950,5500 5950,5416 6024,5342 v1(6024,4209) ; v1(6024,4174) 6024,4124 v1(6121,4027)
  BottomLayer w32: 5491.6,5302.1 T7.2@5551.5,5362 ; 5491.6,5421.9 T7.2@5551.5,5362 ; 5491.6,5578.1 T7.1@5551.5,5638 ; 5491.6,5697.9 T7.1@5551.5,5638 ; 5611.4,5302.1 T7.2@5551.5,5362 ; 5611.4,5421.9 T7.2@5551.5,5362 ; 5611.4,5578.1 T7.1@5551.5,5638 ; 5611.4,5697.9 T7.1@5551.5,5638 ; 5688.6,5302.1 T7.3@5748.5,5362 ; 5688.6,5421.9 T7.3@5748.5,5362 ; 5688.6,5578.1 T7.4@5748.5,5638 ; 5688.6,5697.9 T7.4@5748.5,5638 ; 5808.4,5302.1 T7.3@5748.5,5362 ; 5808.4,5421.9 T7.3@5748.5,5362 ; 5808.4,5578.1 T7.4@5748.5,5638 ; 5808.4,5697.9 T7.4@5748.5,5638
  other v1: 5944,4174 5984,4174 5944,4209 5984,4209
  other v2: 5979,4052 6000,4052.2 6021,4052
VOUT4: C22.1 C23.1 C106.2 C145.1 C146.1 J5.1 T9.1 T9.2 T9.3 T9.4 U4.5 U4.7 | length 4417.6
  TopLayer w12: v1(1879,1973) 1884.5,1967.5 U4.5@1946.9,1967.5
  TopLayer w25: J5.1@1950,500 1950,621.5 C106.2@1968.5,640
  TopLayer w32: 1491.6,302.1 T9.2@1551.5,362 ; 1491.6,421.9 T9.2@1551.5,362 ; 1491.6,578.1 T9.1@1551.5,638 ; 1491.6,697.9 T9.1@1551.5,638 ; 1611.4,302.1 T9.2@1551.5,362 ; 1611.4,421.9 T9.2@1551.5,362 ; 1611.4,578.1 T9.1@1551.5,638 ; 1611.4,697.9 T9.1@1551.5,638 ; 1688.6,302.1 T9.3@1748.5,362 ; 1688.6,421.9 T9.3@1748.5,362 ; 1688.6,578.1 T9.4@1748.5,638 ; 1688.6,697.9 T9.4@1748.5,638 ; 1808.4,302.1 T9.3@1748.5,362 ; 1808.4,421.9 T9.3@1748.5,362 ; 1808.4,578.1 T9.4@1748.5,638 ; 1808.4,697.9 T9.4@1748.5,638
  MidLayer2 w12: v1(1879,1973) 1976,1876 v1(1976,1826) ; J5.1@1950,500 1950,609 1976,635 v1(1976,1791)
  BottomLayer w32: 1491.6,302.1 T9.2@1551.5,362 ; 1491.6,421.9 T9.2@1551.5,362 ; 1491.6,578.1 T9.1@1551.5,638 ; 1491.6,697.9 T9.1@1551.5,638 ; 1611.4,302.1 T9.2@1551.5,362 ; 1611.4,421.9 T9.2@1551.5,362 ; 1611.4,578.1 T9.1@1551.5,638 ; 1611.4,697.9 T9.1@1551.5,638 ; 1688.6,302.1 T9.3@1748.5,362 ; 1688.6,421.9 T9.3@1748.5,362 ; 1688.6,578.1 T9.4@1748.5,638 ; 1688.6,697.9 T9.4@1748.5,638 ; 1808.4,302.1 T9.3@1748.5,362 ; 1808.4,421.9 T9.3@1748.5,362 ; 1808.4,578.1 T9.4@1748.5,638 ; 1808.4,697.9 T9.4@1748.5,638
  other v1: 2016,1791 2056,1791 2016,1826 2056,1826
  other v2: 1979,1948 2000,1947.8 2021,1948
